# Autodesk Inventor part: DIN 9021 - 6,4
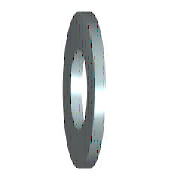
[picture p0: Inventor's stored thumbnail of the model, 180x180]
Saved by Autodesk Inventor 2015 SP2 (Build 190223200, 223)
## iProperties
Created: 2014-02
Part Number: DIN 9021 - 6,4
Material: Stahl, weich
Description: Unterlegscheibe
Document SubType Name: Modeling
Standard: DIN 9021
Designer: rYan
Standards Organization: DIN
Language: de-DE
Size Designation: 6,4
Categories: <MemberInstance><Categories><Category DisplayName="Verbindungselemente" InternalName="e4da775c-781d-43d5-af7c-5136215cf5a6" Mnemonic="FSTN"><Category DisplayNam
Density: 7.85 g/cm^3
Appearance: Halbpoliert
IsCustomPart: 0
Author: rYan
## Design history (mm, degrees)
sketch "Skizze"
  geometry: C1 r 9 at (0, 0); C2 r 3.2 at (0, 0); 1 further point
  constraints: 2 centre point, 2 coincident
  dimensions: "d0" = 6.4 diameter of C2 (= SD1); "d1" = 18 diameter of C1 (= SD2)
extrude "Körper" new body sketch "Skizze" distance "d2" = 1.6 (= SD); taper "d3" = 0 deg
workaxis "Work Axis1"
workplane "Work Plane1"
body "Solid1"
other parameters: "SD1" = 6.4 [user parameter; used in 1 equation term], "SD2" = 18 [user parameter; used in 1 equation term], "SD" = 1.6 [user parameter; used in 1 equation term], "d4" = 0, "d5" = 0, "d6" = 0, "d7" = 0, "NND" = 6 [user parameter]
